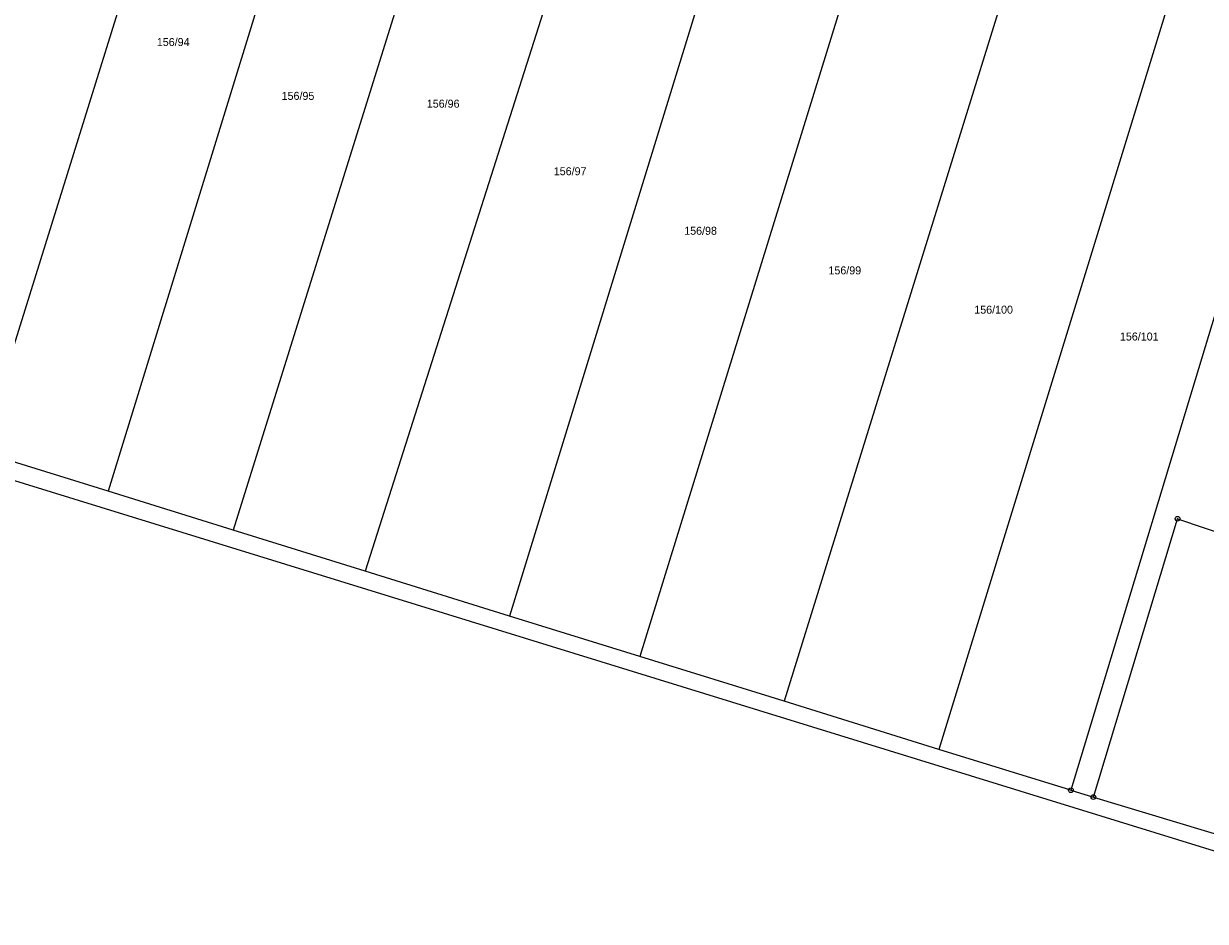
# Model space of a CAD drawing. Extents: x -694609 to -690140, y -1033292 to -1029794.
# Drawn here: x -693359.6 to -693108.5, y -1031718.2 to -1031527.4 of the extents above; entities that cross this region are included whole.
import ezdxf
from ezdxf.enums import TextEntityAlignment as Align

# ---------------------------------------------------------------- set-up
doc = ezdxf.new("R2010")
doc.units = 0
doc.header["$LTSCALE"] = 0.68
doc.layers.add('1', color=7, linetype='Continuous', lineweight=25)
doc.layers.add('8', color=7, linetype='Continuous', lineweight=25)
doc.layers.add('2', color=7, linetype='Continuous')

msp = doc.modelspace()

# ---------------------------------------------------------------- linework, layer by layer
at = {"layer": '1'}
for p, q in [((-693288.88, -1031455.5), (-693341.6, -1031626.81)), ((-693261.5, -1031463.39), (-693315.03, -1031635.06)), ((-693231.42, -1031469.1), (-693287, -1031643.81)), ((-693202.25, -1031477.47), (-693256.34, -1031653.33)), ((-693174.19, -1031485.58), (-693228.65, -1031661.92)), ((-693143.12, -1031494.56), (-693197.95, -1031671.45)), ((-693110.49, -1031504), (-693165.07, -1031681.66)), ((-693092.18, -1031542.05), (-693137.04, -1031690.35)), ((-693058.18, -1031718.22), (-693416.83, -1031607.47)), ((-693341.6, -1031626.81), (-693368.77, -1031618.37)), ((-693315.03, -1031635.06), (-693341.6, -1031626.81)), ((-693132.25, -1031691.79), (-693114.36, -1031632.65)), ((-693114.36, -1031632.65), (-693075.34, -1031646.02)), ((-693287, -1031643.81), (-693315.03, -1031635.06)), ((-693256.34, -1031653.33), (-693287, -1031643.81)), ((-693228.65, -1031661.92), (-693256.34, -1031653.33)), ((-693197.95, -1031671.45), (-693228.65, -1031661.92)), ((-693165.07, -1031681.66), (-693197.95, -1031671.45)), ((-693137.04, -1031690.35), (-693165.07, -1031681.66)), ((-693137.04, -1031690.35), (-693132.25, -1031691.79)), ((-693132.25, -1031691.79), (-693093.2, -1031703.58))]:
    msp.add_line(p, q, dxfattribs=at)
msp.add_lwpolyline([(-693315.6, -1031447.79), (-693368.77, -1031618.37), (-693395.23, -1031610.15)], dxfattribs=at)
at = {"layer": '8'}
for centre, radius in [((-693114.36, -1031632.6499), 0.5), ((-693114.36, -1031632.6499), 0.0303), ((-693137.04, -1031690.3499), 0.5), ((-693137.04, -1031690.3499), 0.0303), ((-693132.25, -1031691.7899), 0.5), ((-693132.25, -1031691.7899), 0.0303)]:
    msp.add_circle(centre, radius, dxfattribs=at)

# ---------------------------------------------------------------- texts
at = {"layer": '2'}
for s, p in [('156/94', (-693327.79, -1031532.175)), ('156/95', (-693301.27, -1031543.615)), ('156/96', (-693270.42, -1031545.275)), ('156/97', (-693243.44, -1031559.635)), ('156/98', (-693215.72, -1031572.285)), ('156/99', (-693185.07, -1031580.705)), ('156/100', (-693153.449, -1031589.055)), ('156/101', (-693122.499, -1031594.765))]:
    msp.add_text(s, height=1.7, dxfattribs=at).set_placement(p, align=Align.CENTER)

doc.saveas('drawing.dxf')
